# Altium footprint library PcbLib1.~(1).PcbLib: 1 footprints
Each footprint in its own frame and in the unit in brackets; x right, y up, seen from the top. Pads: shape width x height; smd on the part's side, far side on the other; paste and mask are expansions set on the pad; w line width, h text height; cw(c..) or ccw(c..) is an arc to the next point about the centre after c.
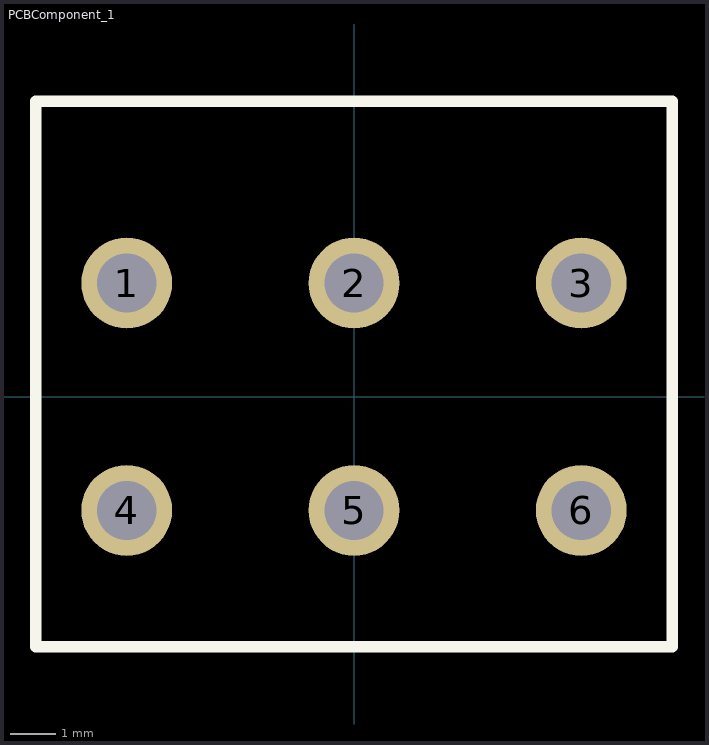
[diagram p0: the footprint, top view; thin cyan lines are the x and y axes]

## PCBComponent_1 [mm]
pads (6):
  round 2 hole 1.3: 1(-5,2.5) 2(0,2.5) 3(5,2.5) 4(-5,-2.5) 5(0,-2.5) 6(5,-2.5)
Top Overlay:
  lines w0.254: -7,-5.5 -7,6.5 7,6.5 7,-5.5 -7,-5.5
